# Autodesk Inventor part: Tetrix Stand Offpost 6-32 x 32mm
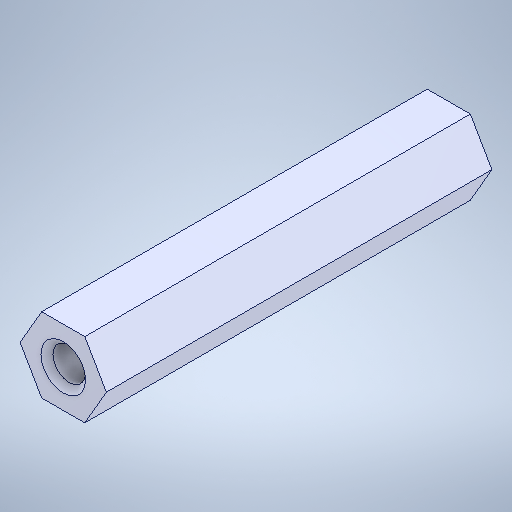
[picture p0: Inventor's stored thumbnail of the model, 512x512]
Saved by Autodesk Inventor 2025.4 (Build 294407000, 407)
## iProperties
Created: 2021-10
Part Number: Tetrix Stand Offpost 6-32 x 32mm
Material: Genérico
Document SubType Name: Modeling
Designer: usuario
Density: 1 g/cm^3
Appearance: Valor por defecto
Author: usuario
Sending System: SolidWorks 2016
Last Author: LENOVO
Last Saved: 2021-10-23
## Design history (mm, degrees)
chamfer "Chamfer1"
node "Plane1"
node "Sólido1"
